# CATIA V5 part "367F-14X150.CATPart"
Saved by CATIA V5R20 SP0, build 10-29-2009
Part number: 367F-14X150
Definition: NONE
Nomenclature: 367F-14X150
Source: Unknown
Description: 367F-14X150
Bounding box of the stored display mesh (mm): x 0 to 150, y -14 to 14, z -14 to 14
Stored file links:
  C:\Users\Utente\Desktop\IO LAVORO\3D X SITO CF\X SITO\PLASTICA\3D files 367\367F-14X150.CATPart
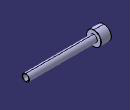
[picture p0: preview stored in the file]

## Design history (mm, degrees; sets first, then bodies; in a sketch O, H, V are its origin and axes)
Body1 "367F-14X150" (main body)
  Solid1: solid without history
